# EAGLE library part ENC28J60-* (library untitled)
Microchip 10Mbit Eth. contoller with SPI interface
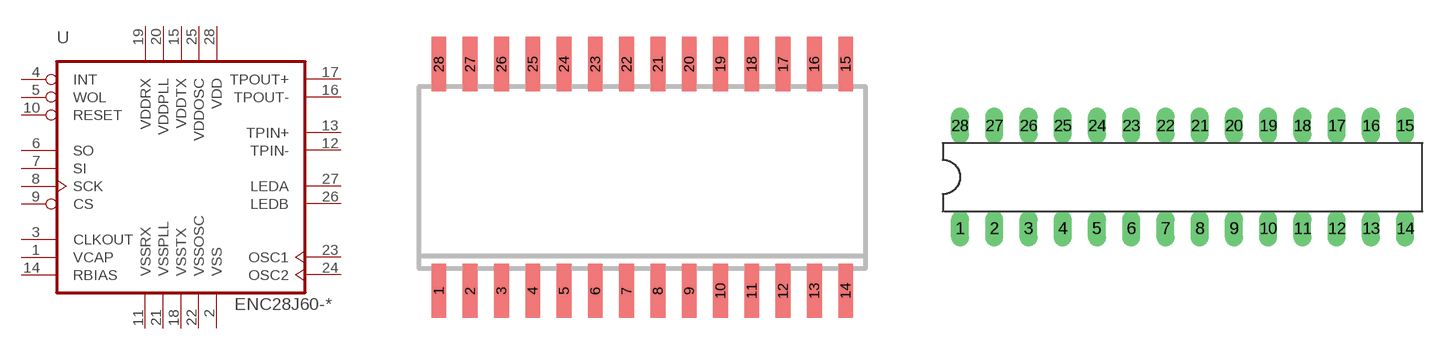
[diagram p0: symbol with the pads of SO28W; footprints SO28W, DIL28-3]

Designator prefix U

## ENC28J60-SO  [SO28W]
1  VCAP  pwr
2  VSS  pwr
3  CLKOUT  out
4  INT  out
5  WOL  out
6  SO  out
7  SI  in
8  SCK  in
9  CS  in
10  RESET  in
11  VSSRX  pwr
12  TPIN-  in
13  TPIN+  in
14  RBIAS  pas
15  VDDTX  pwr
16  TPOUT-  out
17  TPOUT+  out
18  VSSTX  pwr
19  VDDRX  pwr
20  VDDPLL  pwr
21  VSSPLL  pwr
22  VSSOSC  pwr
23  OSC1  in
24  OSC2  out
25  VDDOSC  pwr
26  LEDB  out
27  LEDA  out
28  VDD  pwr

## ENC28J60-DIL  [DIL28-3]
Pads as for SO28W

## ENC28J60-SSOP  [SSOP28]
Pads as for SO28W

## Footprint SO28W (pad centres in mm)
SMALL OUTLINE INTEGRATED CIRCUIT wide body 7.5 mm/JEDEC MO-119AB
smd 0.6 x 2.2: 1 -8.255,-4.6; 2 -6.985,-4.6; 3 -5.715,-4.6; 4 -4.445,-4.6; 5 -3.175,-4.6; 6 -1.905,-4.6; 7 -0.635,-4.6; 8 0.635,-4.6; 9 1.905,-4.6; 10 3.175,-4.6; 11 4.445,-4.6; 12 5.715,-4.6; 13 6.985,-4.6; 14 8.255,-4.6; 15 8.255,4.6; 16 6.985,4.6; 17 5.715,4.6; 18 4.445,4.6; 19 3.175,4.6; 20 1.905,4.6; 21 0.635,4.6; 22 -0.635,4.6; 23 -1.905,4.6; 24 -3.175,4.6; 25 -4.445,4.6; 26 -5.715,4.6; 27 -6.985,4.6; 28 -8.255,4.6

## Footprint DIL28-3 (pad centres in mm)
Dual In Line package type P
drill 0.813 long: 1 -16.51,-3.81; 2 -13.97,-3.81; 3 -11.43,-3.81; 4 -8.89,-3.81; 5 -6.35,-3.81; 6 -3.81,-3.81; 7 -1.27,-3.81; 8 1.27,-3.81; 9 3.81,-3.81; 10 6.35,-3.81; 11 8.89,-3.81; 12 11.43,-3.81; 13 13.97,-3.81; 14 16.51,-3.81; 15 16.51,3.81; 16 13.97,3.81; 17 11.43,3.81; 18 8.89,3.81; 19 6.35,3.81; 20 3.81,3.81; 21 1.27,3.81; 22 -1.27,3.81; 23 -3.81,3.81; 24 -6.35,3.81; 25 -8.89,3.81; 26 -11.43,3.81; 27 -13.97,3.81; 28 -16.51,3.81

## Footprint SSOP28 (pad centres in mm)
Shrink Small Outline Package package type SS
smd 0.4 x 1.5: 1 -4.225,-3.625; 2 -3.575,-3.625; 3 -2.925,-3.625; 4 -2.275,-3.625; 5 -1.625,-3.625; 6 -0.975,-3.625; 7 -0.325,-3.625; 8 0.325,-3.625; 9 0.975,-3.625; 10 1.625,-3.625; 11 2.275,-3.625; 12 2.925,-3.625; 13 3.575,-3.625; 14 4.225,-3.625; 15 4.225,3.625; 16 3.575,3.625; 17 2.925,3.625; 18 2.275,3.625; 19 1.625,3.625; 20 0.975,3.625; 21 0.325,3.625; 22 -0.325,3.625; 23 -0.975,3.625; 24 -1.625,3.625; 25 -2.275,3.625; 26 -2.925,3.625; 27 -3.575,3.625; 28 -4.225,3.625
